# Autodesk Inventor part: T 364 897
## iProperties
Created: 2006-06
Part Number: T 364 897
Material: 1.0120.01
Description: Halteleiste
Vendor: Autodesk Inc.
Document SubType Name: Modeling
Standard: DIN 174
Designer: I.Baliuc
Standards Organization: DIN
Language: de-DE
Size Designation: 40 x 10 - 0.001
Categories: <MemberInstance Version="R10.0.0"><Categories><Category DisplayName="Profilstahle" InternalName="089c4875-fa83-4c05-b084-43b9cc11f5ed" Mnemonic="GRDR"><Category
Density: 7.84 g/cm^3
Mass: 298.545 g
Surface Area: 112.642 cm^2
Volume: 38.0797 cm^3
Zweck: Vorkontakt HSLT
Abmessung: Fl. 40x10-145
G_L: 145,000 mm
Author: T.Messerschmitt
Revision Number: 364897
Keywords: 380109
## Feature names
1. Körper [Extrusion]
2. Bohrung_Ø10 [Hole]
3. Bohrung_Ø8.5 [Hole]
4. Bohr_Ø8.5 [Rectangular Pattern]
